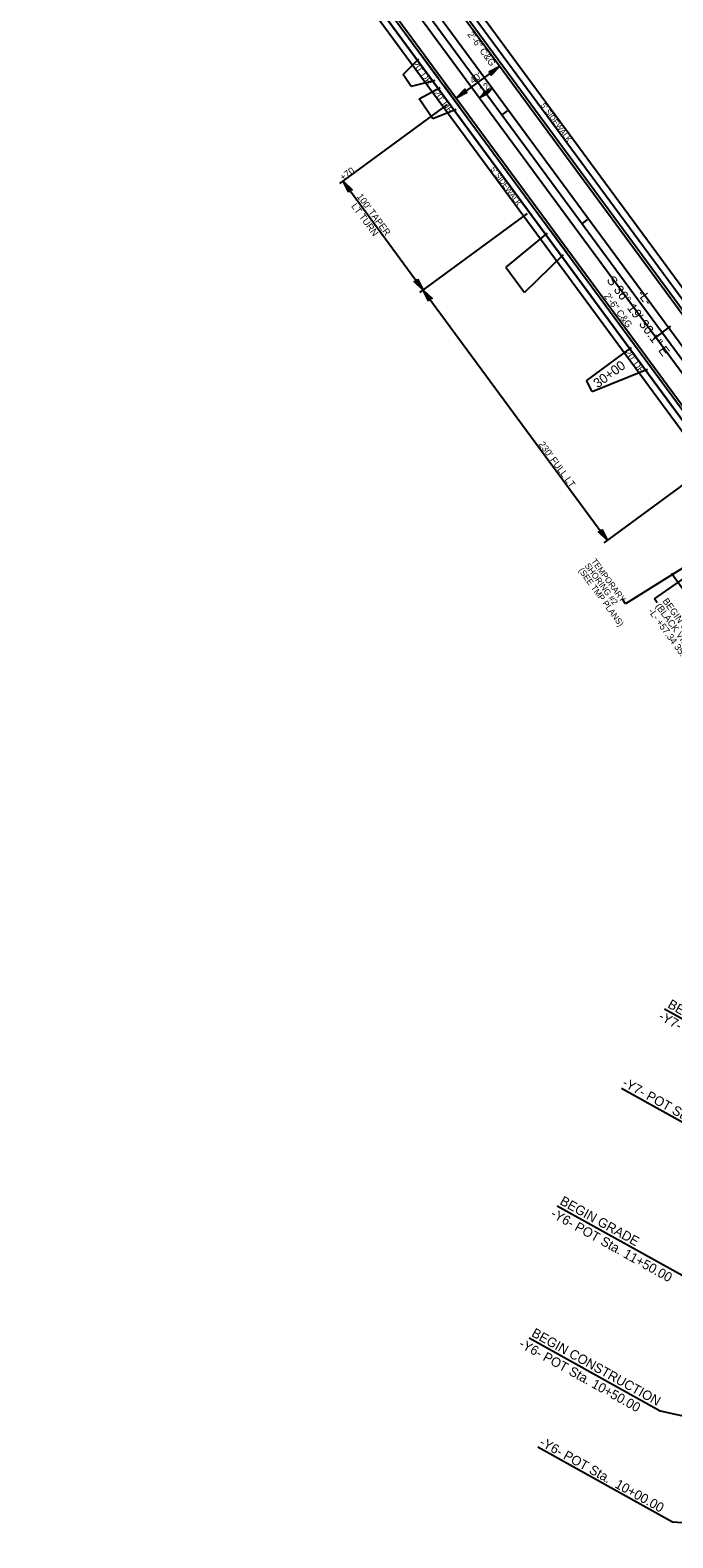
# Model space of a CAD drawing. Extents: x 1762196 to 1766326, y 709922 to 713142.
# Drawn here: x 1763337 to 1763812, y 710885 to 712001 of the extents above; entities that cross this region are included whole.
import ezdxf

# ---------------------------------------------------------------- set-up
doc = ezdxf.new("R2010")
doc.units = 0
for name, color, linetype in [('Old_Level_3', 7, 'Continuous'), ('Pattern 1', 7, 'Continuous'), ('Pattern 2', 7, 'Continuous'), ('Pattern 4', 7, 'Continuous'), ('Prop Conc 2ft 6in Curb and Gutter', 7, 'Continuous'), ('Prop Dimension', 7, 'Continuous'), ('Prop EOT', 7, 'Continuous'), ('Prop Fence Chain Link', 7, 'Continuous'), ('Prop Horizontal Alignment', 7, 'Continuous'), ('Prop Horizontal Alignment Direction Label', 7, 'Continuous'), ('Prop Horizontal Alignment Station Label', 7, 'Continuous'), ('Prop Horizontal Alignment Tick Label', 7, 'Continuous'), ('Prop Horizontal Alignment Tick Large', 7, 'Continuous'), ('Prop Horizontal Alignment Tick Small', 7, 'Continuous'), ('Prop Lane Lines', 7, 'Continuous'), ('Prop Terminator CELL', 7, 'Continuous'), ('Scratch_Level_0', 7, 'Continuous'), ('Scratch_Level_1', 7, 'Continuous')]:
    doc.layers.add(name, color=color, linetype=linetype)

msp = doc.modelspace()

# ---------------------------------------------------------------- linework, layer by layer
at = {"layer": 'Old_Level_3'}
for p, q in [((1763613.1, 711968.5), (1763624.6, 711980)), ((1763618.8, 711959.5), (1763613.1, 711968.5)), ((1763636.5, 711963.9), (1763618.8, 711959.5)), ((1763624.7, 711950.4), (1763640.3, 711958.7)), ((1763634.8, 711935.5), (1763624.7, 711950.4)), ((1763652.1, 711942.6), (1763634.8, 711935.5)), ((1763719.5, 711851), (1763689, 711825.7)), ((1763731.3, 711834.9), (1763702.7, 711807.1)), ((1763689, 711825.7), (1763702.7, 711807.1)), ((1763781.7, 711766.3), (1763748.5, 711742)), ((1763752.8, 711733.8), (1763793.6, 711750.2)), ((1763752.8, 711733.8), (1763748.5, 711742))]:
    msp.add_line(p, q, dxfattribs=at)
at = {"layer": 'Pattern 1'}
for p, q in [((1763337.1, 712360.1), (1763843.8, 711670.9)), ((1763845.5, 711677), (1763341.1, 712363)), ((1763580.1, 712127.5), (1763851.1, 711758.9)), ((1763855.1, 711761.8), (1763584.1, 712130.5))]:
    msp.add_line(p, q, dxfattribs=at)
at = {"layer": 'Pattern 2'}
for p, q in [((1763337.1, 712360.1), (1763843.8, 711670.9)), ((1763341.1, 712363), (1763845.5, 711677)), ((1763580.1, 712127.5), (1763851.1, 711758.9)), ((1763855.1, 711761.8), (1763584.1, 712130.5))]:
    msp.add_line(p, q, dxfattribs=at)
at = {"layer": 'Pattern 4'}
for p, q in [((1763638.9, 711965.6), (1763627, 711981.8)), ((1763654.6, 711944.3), (1763642.7, 711960.5)), ((1763733.7, 711836.6), (1763721.9, 711852.8)), ((1763796, 711752), (1763784.1, 711768.1))]:
    msp.add_line(p, q, dxfattribs=at)
at = {"layer": 'Prop Conc 2ft 6in Curb and Gutter'}
for p, q in [((1763344.8, 712365.7), (1763842.1, 711689.3)), ((1763576.5, 712124.8), (1763847.5, 711756.2))]:
    msp.add_line(p, q, dxfattribs=at)
at = {"layer": 'Prop Dimension'}
for p, q in [((1763684.4, 711974.6), (1763652.2, 711950.9)), ((1763679.1, 711958.3), (1763669.4, 711951.2)), ((1763566.2, 711887.7), (1763645.8, 711946.2)), ((1763568.6, 711889.4), (1763627.8, 711808.9)), ((1763625.4, 711807.1), (1763705, 711865.6)), ((1763627.8, 711808.9), (1763764.1, 711623.6)), ((1763761.7, 711621.8), (1763842.8, 711681.5)), ((1763852.9, 711623.9), (1763777.5, 711576.7)), ((1763798.9, 711580.2), (1763869.6, 711630)), ((1763777.5, 711576.7), (1763775.1, 711580)), ((1763800.9, 711577.3), (1763798.9, 711580.2))]:
    msp.add_line(p, q, dxfattribs=at)
at = {"layer": 'Prop EOT'}
for p, q in [((1763346.4, 712366.9), (1763843.7, 711690.4)), ((1763574.8, 712123.7), (1763845.9, 711755))]:
    msp.add_line(p, q, dxfattribs=at)
at = {"layer": 'Prop Horizontal Alignment'}
msp.add_line((1763362.5, 712378.7), (1764088, 711392), dxfattribs=at)
at = {"layer": 'Prop Horizontal Alignment Station Label'}
for p, q in [((1763806.2, 711276.7), (1763902.9, 711222.9)), ((1763875.4, 711161.6), (1763774.5, 711217.8)), ((1763726.8, 711131.1), (1763823.8, 711077.1)), ((1763706.1, 711033.2), (1763803.1, 710979.2)), ((1763803.1, 710979.2), (1764008.7, 710933.7)), ((1763812.2, 710896.8), (1763712.5, 710952.3)), ((1763996.5, 710885.2), (1763812.2, 710896.8))]:
    msp.add_line(p, q, dxfattribs=at)
at = {"layer": 'Prop Horizontal Alignment Tick Large'}
for q in [(1763798.1, 711772.7), (1763798.1, 711772.7), (1763811, 711782.2), (1763811, 711782.2)]:
    msp.add_line((1763804.6, 711777.5), q, dxfattribs=at)
at = {"layer": 'Prop Horizontal Alignment Tick Small'}
for p, q in [((1763686.1, 711938.6), (1763690.1, 711941.6)), ((1763686.1, 711938.6), (1763690.1, 711941.6)), ((1763745.3, 711858), (1763749.4, 711861)), ((1763745.3, 711858), (1763749.4, 711861))]:
    msp.add_line(p, q, dxfattribs=at)
at = {"layer": 'Prop Lane Lines'}
for p, q in [((1763367.3, 712382.3), (1763916.5, 711635.3)), ((1763357.6, 712375.2), (1763906.9, 711628.2))]:
    msp.add_line(p, q, dxfattribs=at)
at = {"layer": 'Prop Terminator CELL'}
for points in [[(1763676.3, 711970.5), (1763684.4, 711974.6), (1763678.1, 711968), (1763678.1, 711969.9)], [(1763660.4, 711955), (1763652.2, 711950.9), (1763658.5, 711957.6), (1763658.6, 711955.6)], [(1763674.2, 711955.8), (1763679.1, 711958.3), (1763675.3, 711954.3), (1763675.3, 711955.5)], [(1763674.3, 711953.6), (1763669.4, 711951.2), (1763673.2, 711955.1), (1763673.2, 711954)], [(1763572.7, 711881.3), (1763568.6, 711889.4), (1763575.2, 711883.1), (1763573.3, 711883.1)], [(1763623.7, 711817), (1763627.8, 711808.9), (1763621.2, 711815.2), (1763623.2, 711815.2)], [(1763631.9, 711800.7), (1763627.8, 711808.9), (1763634.5, 711802.5), (1763632.5, 711802.5)], [(1763760, 711631.7), (1763764.1, 711623.6), (1763757.4, 711629.9), (1763759.4, 711629.9)]]:
    msp.add_lwpolyline(points, close=True, dxfattribs=at)
at = {"layer": 'Scratch_Level_0'}
msp.add_line((1763811.5, 711599.3), (1763877.1, 711507.8), dxfattribs=at)
at = {"layer": 'Scratch_Level_1'}
msp.add_line((1763808.9, 711781.7), (1763808.9, 711781.6), dxfattribs=at)

# ---------------------------------------------------------------- texts
at = {"layer": 'Prop Dimension'}
for s, height, rotation, p in [('2\'-6" C&G', 5, 306.2561, (1763660.2, 711998)), ("20' DR", 5, 306.0767, (1763619.4, 711976.3)), ("40'", 5, 36.325, (1763664.6, 711961.2)), ("20' DR", 5, 306.0767, (1763635.1, 711955)), ("12'", 5, 36.325, (1763671.5, 711954.3)), ("5' SIDEWALK", 4, 306.3161, (1763714.4, 711945.5)), ("5' SIDEWALK", 4, 306.3161, (1763677.3, 711898.4)), ('+70', 5, 36.325, (1763568.4, 711889.5)), ("100' TAPER", 5, 306.325, (1763578.4, 711878)), ('LT TURN', 5, 306.325, (1763574.3, 711870.9)), ('2\'-6" C&G', 5, 306.2561, (1763761.3, 711804.3)), ("20' DR", 5, 306.0767, (1763776.5, 711762.6)), ("230' FULL LT", 5, 306.325, (1763712.9, 711694.6)), ('TEMPORARY ', 4.5, 306.2176, (1763751.8, 711608.1)), ('(SEE TMP PLANS)', 4.5, 306.2176, (1763742.3, 711601.2)), ('SHORING #2', 4.5, 306.2176, (1763747, 711604.7))]:
    msp.add_text(s, height=height, rotation=rotation, dxfattribs=at).set_placement(p)
at = {"layer": 'Prop Fence Chain Link'}
for s, p in [('(BLACK VINYL)', (1763799.3, 711574.8)), ('BEGIN CL FENCE', (1763804.5, 711578.6)), ("-L- +57.34 35.00'", (1763794, 711571))]:
    msp.add_text(s, height=5, rotation=305.9055, dxfattribs=at).set_placement(p)
at = {"layer": 'Prop Horizontal Alignment Direction Label'}
for s, p in [('S 36%%d 19\' 30.1" E', (1763763.1, 711816.2)), ('-L-', (1763785.7, 711806.1))]:
    msp.add_text(s, height=7, rotation=306.325, dxfattribs=at).set_placement(p)
at = {"layer": 'Prop Horizontal Alignment Station Label'}
for s, p in [('BEGIN CONSTRUCTION', (1763808, 711278.1)), ('-Y7- POT Sta. 10+15.00', (1763801.3, 711269.3)), ('-Y7- POT Sta.  10+00.00', (1763774.4, 711220.1)), ('BEGIN GRADE', (1763728.3, 711132.5)), ('-Y6- POT Sta. 11+50.00', (1763721.5, 711123.2)), ('-Y6- POT Sta. 10+50.00', (1763698, 711026.9)), ('BEGIN CONSTRUCTION', (1763707.3, 711034.8)), ('-Y6- POT Sta.  10+00.00', (1763713.1, 710954))]:
    msp.add_text(s, height=7, rotation=330.8875, dxfattribs=at).set_placement(p)
at = {"layer": 'Prop Horizontal Alignment Tick Label'}
msp.add_text('30+00', height=7, rotation=36.325, dxfattribs=at).set_placement((1763756.9, 711736))

doc.saveas('drawing.dxf')
